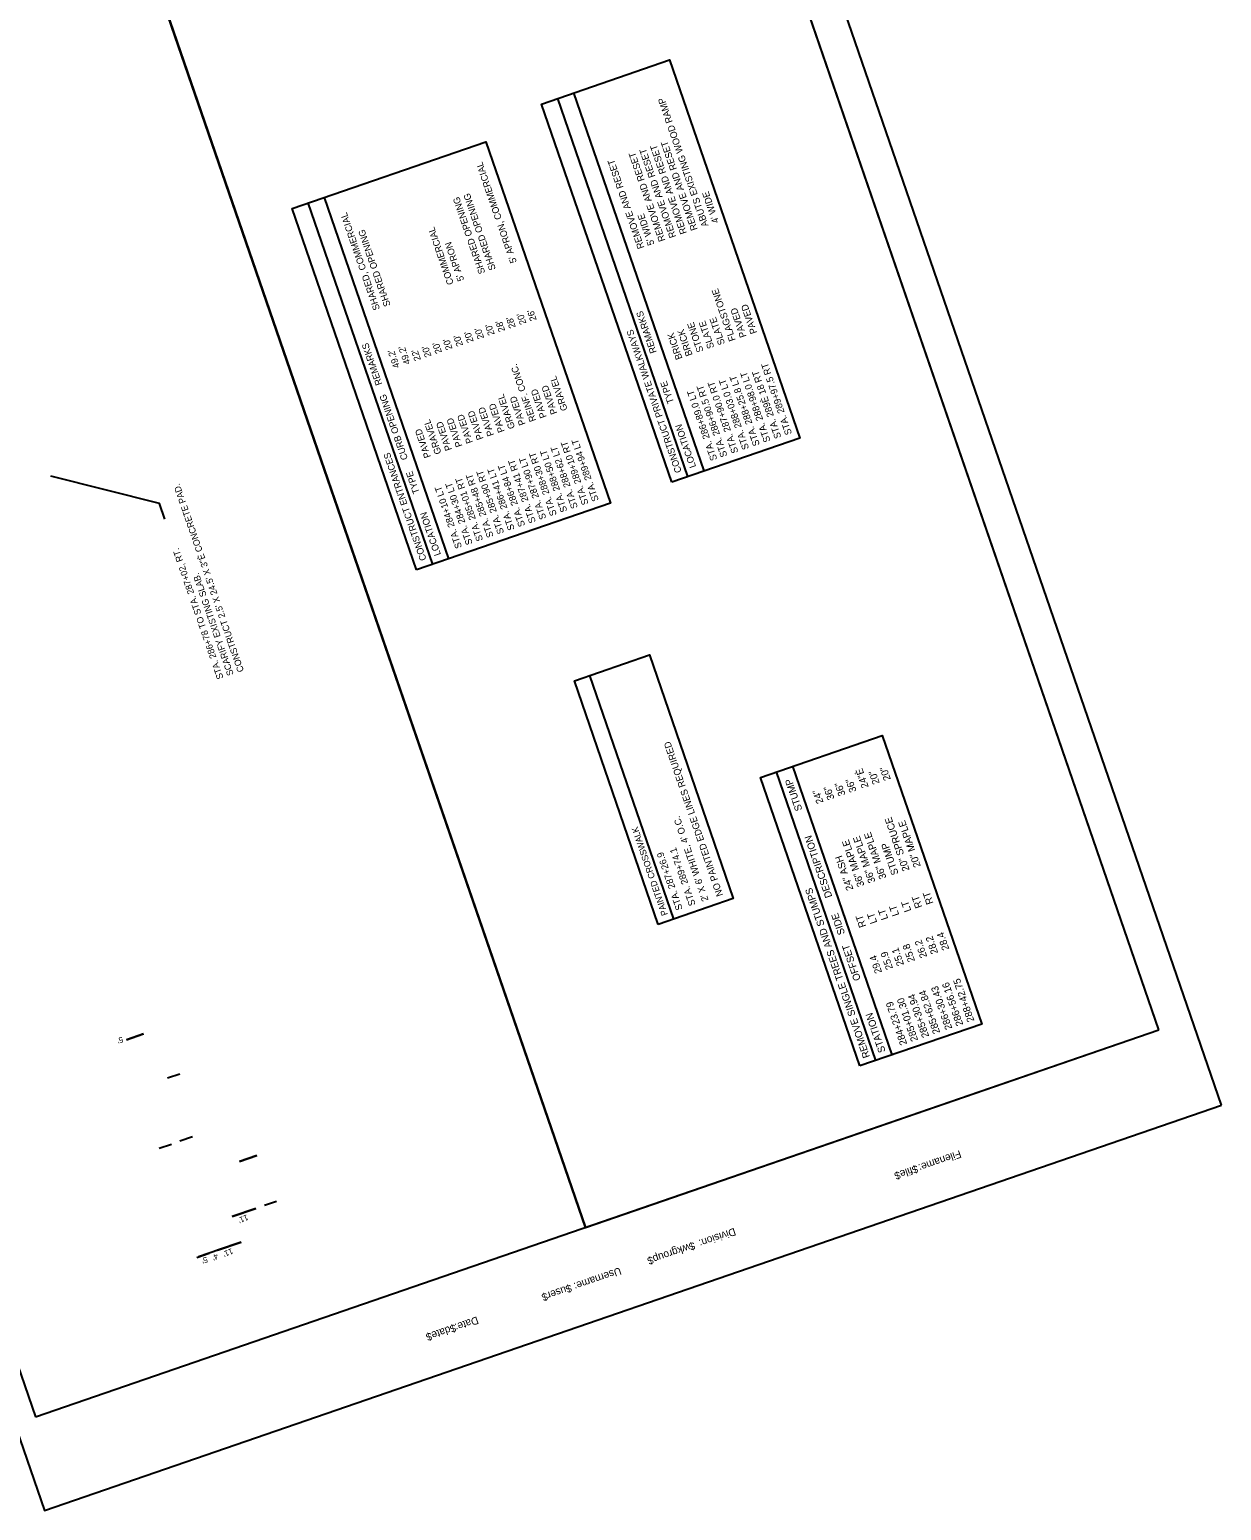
# Model space of a CAD drawing. Extents: x 1111039 to 1111836, y 617707 to 618690.
# Drawn here: x 1111309 to 1111836, y 617707 to 618362 of the extents above; entities that cross this region are included whole.
import ezdxf

# ---------------------------------------------------------------- set-up
doc = ezdxf.new("R2010")
doc.units = 0
for name, color, linetype in [('MINOR', 7, 'Continuous'), ('S_Roadway_Sidewalks_Paved', 7, 'Continuous'), ('S_Utilities_GuyWire3', 7, 'Continuous'), ('SHADING', 7, 'Continuous')]:
    doc.layers.add(name, color=color, linetype=linetype)

msp = doc.modelspace()

# ---------------------------------------------------------------- linework, layer by layer
at = {"layer": 'MINOR'}
for p, q in [((1111807.98, 617919.56), (1111547.52, 618675.97)), ((1111554.58, 617832.3), (1111310.4, 618541.44)), ((1111051.13, 618505.05), (1111311.58, 617748.63)), ((1111311.58, 617748.63), (1111807.98, 617919.56))]:
    msp.add_line(p, q, dxfattribs=at)
at = {"layer": 'S_Roadway_Sidewalks_Paved'}
msp.add_lwpolyline([(1111835.61, 617886.27), (1111558.88, 618689.96), (1111038.85, 618510.9), (1111315.58, 617707.21)], close=True, dxfattribs=at)
at = {"layer": 'S_Utilities_GuyWire3'}
for p, q in [((1111607.08, 618166.58), (1111549.54, 618333.68)), ((1111599.92, 618164.11), (1111542.38, 618331.21)), ((1111494.34, 618127.76), (1111439.35, 618287.47)), ((1111487.17, 618125.29), (1111432.18, 618285.01)), ((1111593.63, 617968.5), (1111556.54, 618076.23)), ((1111682.98, 617906.07), (1111639.08, 618033.58)), ((1111690.15, 617908.54), (1111646.24, 618036.05)), ((1111359.43, 617917.77), (1111351.84, 617915.24)), ((1111351.84, 617915.24), (1111359.43, 617917.77)), ((1111375.36, 617899.99), (1111370.01, 617898.16)), ((1111366.31, 617867.25), (1111371.66, 617869.11)), ((1111381, 617872.33), (1111375.45, 617870.4)), ((1111401.8, 617861.38), (1111409.36, 617864)), ((1111409.36, 617864), (1111401.8, 617861.38)), ((1111398.58, 617837.02), (1111408.97, 617840.63)), ((1111408.97, 617840.63), (1111398.58, 617837.02)), ((1111418.1, 617843.77), (1111412.75, 617841.94)), ((1111382.97, 617819.01), (1111388.32, 617820.87)), ((1111392.09, 617822.2), (1111402.5, 617825.75)), ((1111402.5, 617825.73), (1111392.09, 617822.18))]:
    msp.add_line(p, q, dxfattribs=at)
for points in [[(1111592.75, 618161.65), (1111535.22, 618328.75), (1111591.77, 618348.22), (1111649.31, 618181.12)], [(1111480.01, 618122.83), (1111425.02, 618282.54), (1111510.66, 618312.03), (1111565.65, 618152.31)], [(1111586.83, 617966.16), (1111549.74, 618073.89), (1111582.86, 618085.29), (1111619.95, 617977.56)], [(1111675.82, 617903.61), (1111631.91, 618031.11), (1111685.8, 618049.67), (1111729.71, 617922.16)]]:
    msp.add_lwpolyline(points, close=True, dxfattribs=at)
for points in [[(1111368.78, 618145.26), (1111366.38, 618152.26), (1111318.46, 618164.3)], [(1111402.49, 617825.78), (1111383.59, 617819.23)]]:
    msp.add_lwpolyline(points, dxfattribs=at)
at = {"layer": 'SHADING'}
msp.add_lwpolyline([(1111807.98, 617919.56), (1111563.8, 618628.7), (1111310.4, 618541.44), (1111554.58, 617832.3)], close=True, dxfattribs=at)

# ---------------------------------------------------------------- texts
at = {"layer": 'MINOR'}
for s, p in [('Filename:', (1111719.98, 617866.44)), ('$file$', (1111700.95, 617859.88)), ('Division:', (1111620.38, 617832.14)), ('$wkgroup$', (1111602.4, 617825.95)), ('Username:', (1111569.79, 617814.72)), ('$user$', (1111547.93, 617807.2)), ('$date$', (1111496.81, 617789.59)), ('Date:', (1111506.68, 617792.99))]:
    msp.add_text(s, height=3.348, rotation=199, dxfattribs=at).set_placement(p)
at = {"layer": 'S_Utilities_GuyWire3'}
for s, height, rotation, p in [('ABUTS EXISTING WOOD RAMP', 3.0059, 109, (1111609, 618275.05)), ('REMOVE AND RESET', 3.0059, 109, (1111604.22, 618273.41)), ('REMOVE AND RESET', 3.0059, 109, (1111590.01, 618268.52)), ('REMOVE AND RESET', 3.0059, 109, (1111594.75, 618270.15)), ('REMOVE AND RESET', 3.0059, 109, (1111599.49, 618271.78)), ("5' APRON, COMMERCIAL", 2.9531, 109, (1111524.32, 618259)), ('REMOVE AND RESET', 3.0059, 109, (1111580.69, 618265.31)), ('SHARED OPENING', 2.9531, 109, (1111510.4, 618254.21)), ('SHARED OPENING', 2.9531, 109, (1111515.06, 618255.82)), ("4' WIDE", 3.006, 109, (1111613.7, 618276.67)), ('SHARED, COMMERCIAL', 2.9531, 109, (1111463.87, 618238.19)), ("5' WIDE", 3.006, 109, (1111585.16, 618266.84)), ('SHARED OPENING', 2.9531, 109, (1111468.57, 618239.81)), ('COMMERCIAL', 2.953, 109, (1111496.49, 618249.42)), ("5' APRON", 2.953, 109, (1111501.09, 618251.01)), ('FLAGSTONE', 3.006, 109, (1111621.08, 618224.46)), ('PAVED', 3.006, 109, (1111630.55, 618227.72)), ("28'", 2.953, 109, (1111523.87, 618230.21)), ("20'", 2.953, 109, (1111528.6, 618231.84)), ("26'", 2.953, 109, (1111533.14, 618233.4)), ('LOCATION         TYPE            REMARKS', 2.9531, 109, (1111603.57, 618168.49)), ('SLATE', 3.006, 109, (1111616.34, 618222.83)), ('PAVED', 3.006, 109, (1111625.86, 618226.11)), ("20'", 2.953, 109, (1111505.3, 618223.82)), ("20'", 2.953, 109, (1111509.91, 618225.4)), ("20'", 2.953, 109, (1111514.57, 618227)), ("28'", 2.953, 109, (1111519.22, 618228.61)), ('CONSTRUCT PRIVATE WALKWAYS', 2.9531, 109, (1111597.21, 618166.3)), ('BRICK', 3.006, 109, (1111597.55, 618216.36)), ('BRICK', 3.006, 109, (1111602.01, 618217.9)), ('STONE', 3.006, 109, (1111606.87, 618219.57)), ('SLATE', 3.006, 109, (1111611.6, 618221.2)), ('LOCATION        TYPE     CURB OPENING    REMARKS', 2.9531, 109, (1111490.82, 618129.67)), ("49.2'", 2.953, 109, (1111477.39, 618214.2)), ("20'", 2.953, 109, (1111486.64, 618217.39)), ("20'", 2.953, 109, (1111491.3, 618218.99)), ("20'", 2.953, 109, (1111495.95, 618220.6)), ("20'", 2.953, 109, (1111500.6, 618222.2)), ("49.2'", 2.953, 109, (1111472.68, 618212.58)), ("22'", 2.953, 109, (1111481.99, 618215.79)), ('REINF. CONC.', 2.9531, 109, (1111532.89, 618188.91)), ('STA. 289+97.5 RT', 3.0059, 109, (1111645.93, 618183.07)), ('GRAVEL', 2.953, 109, (1111546.8, 618193.7)), ('STA. 288+25.8 LT', 3.0059, 109, (1111631.72, 618178.18)), ('STA. 288+98.0 LT', 3.0059, 109, (1111636.45, 618179.81)), ('STA. 289È 18 RT', 3.0059, 109, (1111641.23, 618181.46)), ('GRAVEL', 2.953, 109, (1111523.58, 618185.71)), ('PAVED', 2.953, 109, (1111537.54, 618190.51)), ('PAVED', 2.953, 109, (1111542.27, 618192.14)), ('STA. 286+89.0 LT', 3.0059, 109, (1111612.92, 618171.71)), ('STA. 286+90.5 RT', 3.0059, 109, (1111617.38, 618173.25)), ('STA. 287+90.0 RT', 3.0059, 109, (1111622.24, 618174.92)), ('STA. 288+03.0 LT', 3.0059, 109, (1111626.98, 618176.55)), ('PAVED', 2.953, 109, (1111514.27, 618182.5)), ('PAVED', 2.953, 109, (1111518.97, 618184.12)), ('PAVED', 2.953, 109, (1111528.23, 618187.31)), ('GRAVEL', 2.953, 109, (1111491.05, 618174.51)), ('PAVED', 2.953, 109, (1111495.66, 618176.09)), ('PAVED', 2.953, 109, (1111500.31, 618177.69)), ('PAVED', 2.953, 109, (1111504.97, 618179.3)), ('PAVED', 2.953, 109, (1111509.62, 618180.9)), ('PAVED', 2.953, 109, (1111486.35, 618172.89)), ('CONSTRUCT ENTRANCES', 2.9531, 109, (1111484.46, 618127.48)), ('STA. 288+30 RT', 2.9531, 109, (1111542.01, 618147.29)), ('STA. 288+50 LT', 2.9531, 109, (1111546.67, 618148.9)), ('STA. 288+62 LT', 2.9531, 109, (1111551.32, 618150.5)), ('STA. 289+10 RT', 2.9531, 109, (1111556.05, 618152.13)), ('STA. 289+94 LT', 2.9531, 109, (1111560.58, 618153.69)), ('STA. 286+84 LT', 2.9531, 109, (1111528.05, 618142.49)), ('STA. 287+41 RT', 2.9531, 109, (1111532.75, 618144.1)), ('STA. 287+90 LT', 2.9531, 109, (1111537.36, 618145.69)), ('STA. 285+01 RT', 2.9531, 109, (1111509.44, 618136.08)), ('STA. 285+48 RT', 2.9531, 109, (1111514.09, 618137.68)), ('STA. 285+90 RT', 2.9531, 109, (1111518.74, 618139.28)), ('STA. 286+41 LT', 2.9531, 109, (1111523.4, 618140.88)), ('CONSTRUCT 2.5\' X 24.5\' X 3"È CONCRETE PAD.', 2.88, 109, (1111403.81, 618078.24)), ('STA. 284+10 LT', 2.9531, 109, (1111500.13, 618132.87)), ('STA. 284+30 LT', 2.9531, 109, (1111504.83, 618134.49)), ('STA.', 2.953, 109, (1111556.05, 618152.13)), ('STA. 286+78 TO STA. 287+02, RT.', 2.88, 109, (1111394.73, 618075.11)), ('SCARIFY EXISTING SLAB.', 2.88, 109, (1111399.27, 618076.68)), ('NO PAINTED EDGE LINES REQUIRED', 3.0059, 108.99894, (1111615.51, 617979.13)), ('24"È', 3.164, 109, (1111679.82, 618026.99)), ('20"', 3.164, 109, (1111684.68, 618028.66)), ('20"', 3.164, 109, (1111689.59, 618030.35)), ('STUMP', 3.164, 109, (1111650.51, 618016.9)), ('24"', 3.164, 109, (1111659.87, 618020.12)), ('36"', 3.164, 109, (1111664.73, 618021.79)), ('36"', 3.164, 109, (1111669.6, 618023.47)), ('36"', 3.164, 109, (1111674.46, 618025.14)), ("2' X 6' WHITE, 4' O.C.", 3.0059, 108.99894, (1111609.07, 617976.92)), ('20" SPRUCE', 3.164, 109, (1111697.89, 617990.28)), ('20" MAPLE', 3.164, 109, (1111702.81, 617991.98)), ('PAINTED CROSSWALK', 2.8055, 108.99894, (1111591.06, 617970.58)), ('DESCRIPTION', 3.1641, 109, (1111663.73, 617978.52)), ('36" MAPLE', 3.164, 109, (1111682.81, 617985.09)), ('36" MAPLE', 3.164, 109, (1111687.68, 617986.77)), ('STA. 287+26.9', 3.0059, 108.99894, (1111597.66, 617972.99)), ('STA. 289+74.1', 3.0059, 108.99894, (1111603.36, 617974.95)), ('36" MAPLE', 3.164, 109, (1111677.95, 617983.42)), ('STUMP', 3.164, 109, (1111693.03, 617988.61)), ('24" ASH', 3.164, 109, (1111673.09, 617981.74)), ('REMOVE SINGLE TREES AND STUMPS', 3.1641, 109, (1111680.4, 617907.73)), ('RT', 3.164, 109, (1111703.52, 617973.93)), ('RT', 3.164, 109, (1111708.44, 617975.62)), ('LT', 3.164, 109, (1111688.44, 617968.74)), ('LT', 3.164, 109, (1111693.31, 617970.41)), ('LT', 3.164, 109, (1111698.66, 617972.26)), ('SIDE', 3.164, 109, (1111669.36, 617962.17)), ('RT', 3.164, 109, (1111678.72, 617965.39)), ('LT', 3.164, 109, (1111683.58, 617967.06)), ('26.2', 3.164, 109, (1111705.66, 617951.94)), ('28.2', 3.164, 109, (1111710.52, 617953.62)), ('28.4', 3.164, 109, (1111715.43, 617955.31)), ('OFFSET', 3.164, 109, (1111676.35, 617941.86)), ('29.4', 3.164, 109, (1111685.71, 617945.08)), ('25.9', 3.164, 109, (1111690.57, 617946.75)), ('25.1', 3.164, 109, (1111695.44, 617948.43)), ('25.8', 3.164, 109, (1111700.3, 617950.1)), ('286+30.43', 3.164, 109, (1111716.76, 617920.24)), ('286+56.16', 3.164, 109, (1111721.62, 617921.92)), ('288+42.75', 3.164, 109, (1111726.53, 617923.61)), ('285+01.30', 3.164, 109, (1111701.68, 617915.05)), ('285+30.94', 3.164, 109, (1111706.54, 617916.73)), ('285+62.84', 3.164, 109, (1111711.4, 617918.4)), ('STATION', 3.164, 109, (1111687.29, 617910.1)), ('284+23.79', 3.164, 109, (1111696.81, 617913.38)), ("5'", 2.55, 196.99154, (1111349.92, 617916.67)), ("11'", 2.55, 202.3309, (1111405, 617838.05)), ("11'", 2.55, 202.3309, (1111398.29, 617823.13)), ("5'", 2.55, 196.99154, (1111387.24, 617819.44)), ("4'", 2.55, 203.28557, (1111391.73, 617820.9))]:
    msp.add_text(s, height=height, rotation=rotation, dxfattribs=at).set_placement(p)

doc.saveas('drawing.dxf')
